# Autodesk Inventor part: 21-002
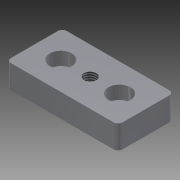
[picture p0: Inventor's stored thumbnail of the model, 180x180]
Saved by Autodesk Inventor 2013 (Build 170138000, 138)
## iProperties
Created: 2004-10
Part Number: 21-002
Material: Stahl (hohe Festigk., niedr. Legier.)
Document SubType Name: Modeling
Designer: Autodesk, Inc.
Manufacturer: Standard
Standards Organization: Custom
Description: BASE PLATE, 40 SERIES, 40x80, M10
Vendor: PARKER IPS
Catalog Web Link: http://www.parker.com/ead/cm1.asp?cmid=809
Mass: 320.354 g
Surface Area: 105.96 cm^2
Volume: 40.8615 cm^3
Density: 7.84 g/cm^3
CAGE: 1LJX3
Dept. ID: Product Design
Description #2: ---
Finish #1: ---
Finish #2: ---
Material ID: ---
Project Number: ---
Author: Autodesk, Inc.
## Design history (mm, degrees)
derived "21-XXX Mounting Plates.ipt"
body "Solid1"
tag "TaggingFeature2"
feature "Solid1::21-XXX Mounting Plates.ipt" dims "ScaleForDerivedMember" = 10
